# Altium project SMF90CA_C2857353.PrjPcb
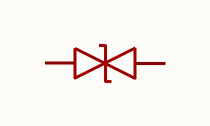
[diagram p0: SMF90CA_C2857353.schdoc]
1 sheet, 1 parts. Net scope: global (net labels, ports and power ports of the same name join across sheets).

## Sheet SMF90CA_C2857353.schdoc
size 127 x 101 mm

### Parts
D?  smf90ca_c2857353  [SOD-123FL_L2.8-W1.8-LS3.7-BI]  (value not drawn)

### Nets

Not connected (* = marked no-connect by the designer): D? 1 2

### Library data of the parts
D? = smf90ca_c2857353: 极性:双向;反向截止电压(Vrwm):90V;钳位电压:146V;峰值脉冲电流(Ipp):1.4A;峰值脉冲功率(Ppp):200W@10/1000us;击穿电压(VBR):100V;; Manufacturer: JSMSEMI(杰盛微); AddInBom: yes; ModelId: d105299b3871451c86f679efef28ff8f; ModelTransform: 145.669,70.866,0,0,0,0,0,0,0; Polarity: 双向; Reverse Stand-Off Voltage (Vrwm): 90V; Clamping Voltage: 146V; Peak Pulse Current (Ipp): 1.4A; Voltage - Breakdown: 100V; Reverse Leakage Current (Ir): 1uA; Number of Channels: 单路; Type: TVS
